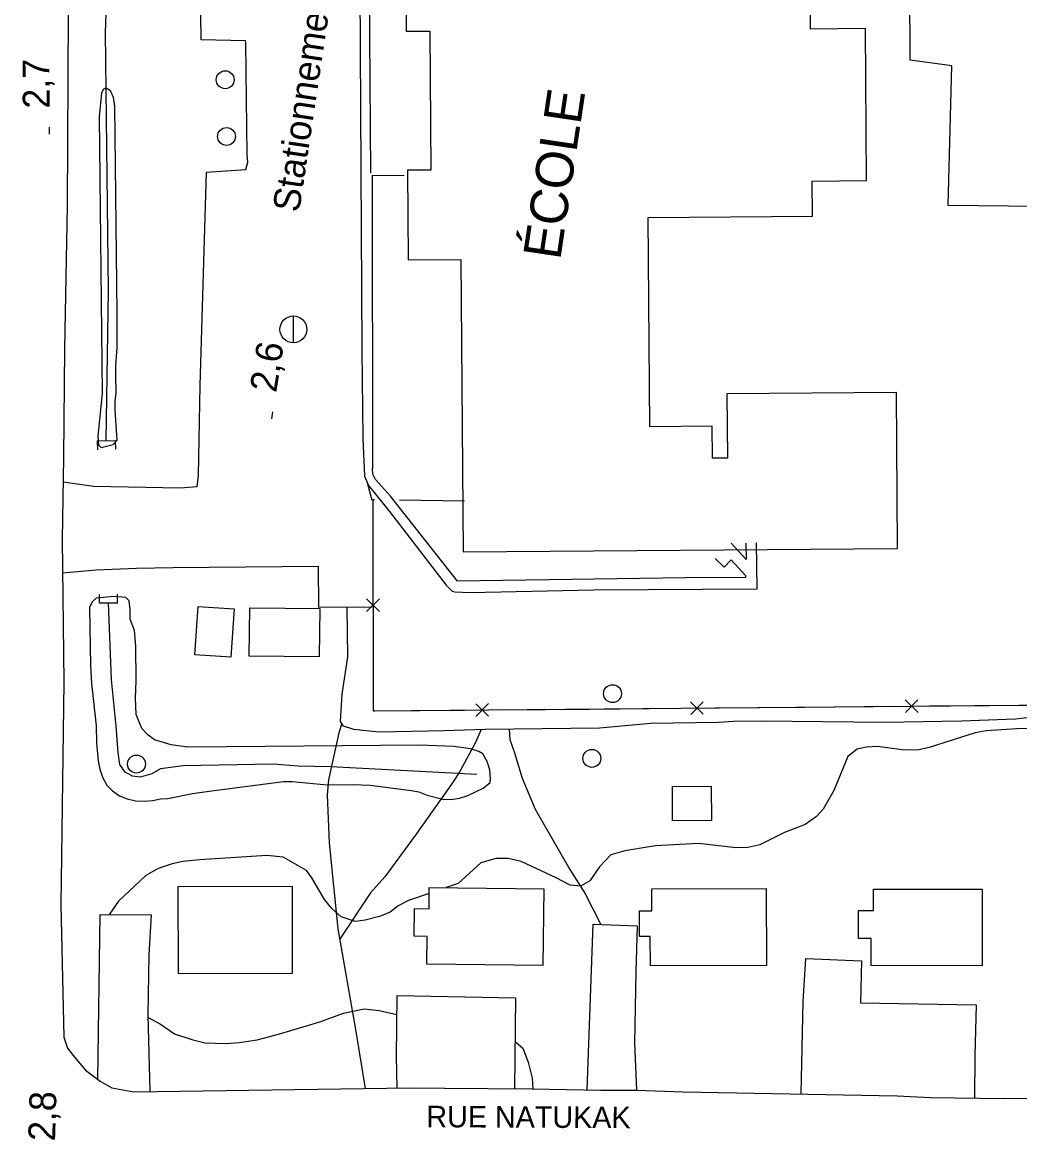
# Model space of a CAD drawing. Extents: x 282461 to 284471, y 5554090 to 5557646.
# Drawn here: x 283061.4 to 283172.9, y 5555298.4 to 5555423.2 of the extents above; entities that cross this region are included whole.
import ezdxf

# ---------------------------------------------------------------- set-up
doc = ezdxf.new("R2010")
doc.units = 0
for name, color, linetype in [('Niveau 15', 7, 'Continuous'), ('Niveau 19', 7, 'Continuous'), ('Niveau 2', 7, 'Continuous'), ('Niveau 21', 7, 'Continuous'), ('Niveau 22', 7, 'Continuous'), ('Niveau 26', 7, 'Continuous'), ('Niveau 3', 7, 'Continuous'), ('Niveau 31', 7, 'Continuous'), ('Niveau 36', 7, 'Continuous'), ('Niveau 37', 7, 'Continuous'), ('Niveau 4', 7, 'Continuous'), ('Niveau 52', 7, 'Continuous'), ('Niveau 56', 7, 'Continuous')]:
    doc.layers.add(name, color=color, linetype=linetype)

msp = doc.modelspace()

# ---------------------------------------------------------------- linework, layer by layer
at = {"layer": 'Niveau 19'}
for points in [[(283080.95, 5555371.34), (283079.03, 5555371.2), (283069.35, 5555371.38), (283065.96, 5555371.87)], [(283065.88, 5555361.73), (283069.65, 5555362.07), (283074.17, 5555362.23), (283078.23, 5555362.33), (283094.46, 5555362.46), (283094.52, 5555357.87), (283100.49, 5555357.94)], [(283069.84, 5555305.12), (283070.11, 5555323.54), (283075.79, 5555323.48), (283075.56, 5555319.02), (283075.45, 5555312.32), (283075.66, 5555303.75)], [(283124.54, 5555303.94), (283125.2, 5555322.46), (283130.13, 5555322.28), (283129.96, 5555317.12), (283129.83, 5555309.17), (283130.06, 5555303.9)], [(283148.44, 5555303.5), (283148.68, 5555313.8), (283148.97, 5555318.62), (283155.19, 5555318.36), (283155.07, 5555313.67), (283168.01, 5555313.43), (283167.85, 5555307.74), (283167.83, 5555303.01)], [(283103.3, 5555304.13), (283103.21, 5555307.67), (283103.31, 5555314.48), (283116.54, 5555314.22), (283116.42, 5555304.08)]]:
    msp.add_lwpolyline(points, dxfattribs=at)
at = {"layer": 'Niveau 2'}
for points in [[(283071.86, 5555383.86), (283071.85, 5555384.91), (283072, 5555386.88), (283072.01, 5555390.71), (283071.73, 5555413.87), (283071.6, 5555414.85), (283071.25, 5555415.6), (283070.78, 5555415.89), (283070.49, 5555415.77), (283070.26, 5555415.36), (283070, 5555412.69), (283070.32, 5555381.76), (283069.86, 5555376.99), (283069.93, 5555376.01), (283070.22, 5555375.72), (283071.55, 5555376.08), (283072.01, 5555376.55), (283071.8, 5555379.92), (283071.78, 5555380.9), (283071.89, 5555381.83), (283071.86, 5555383.86)], [(283073.47, 5555356.55), (283073.46, 5555357.59), (283073.33, 5555358.58), (283072.98, 5555358.98), (283071.58, 5555359.08), (283069.67, 5555358.88), (283069.21, 5555358.47), (283068.93, 5555357.83), (283069.01, 5555351.33), (283069.15, 5555349.36), (283069.67, 5555344.61), (283069.69, 5555342.69), (283069.89, 5555340.72), (283070.08, 5555339.79), (283070.38, 5555338.87), (283070.85, 5555338), (283071.5, 5555337.37), (283072.26, 5555336.8), (283073.14, 5555336.46), (283074.07, 5555336.24), (283075.05, 5555336.19), (283075.98, 5555336.26), (283076.85, 5555336.45), (283077.66, 5555336.51), (283080.44, 5555337.06), (283082.29, 5555337.32), (283090.58, 5555338.39), (283091.56, 5555338.41), (283095.46, 5555338.04), (283098.36, 5555338.07), (283100.27, 5555337.98), (283104.86, 5555337.39), (283105.74, 5555337.23), (283106.67, 5555336.89), (283108.42, 5555336.44), (283109.35, 5555336.4), (283110.27, 5555336.52), (283111.2, 5555336.82), (283112.93, 5555337.65), (283113.68, 5555338.3), (283113.73, 5555338.71), (283113.66, 5555339.69), (283113.36, 5555340.62), (283112.88, 5555341.48), (283112.41, 5555341.77), (283111.48, 5555342.05), (283109.62, 5555342.32), (283105.79, 5555342.45), (283079.91, 5555342.22), (283078.05, 5555342.49), (283076.19, 5555343.05), (283075.43, 5555343.63), (283074.78, 5555344.31), (283074.12, 5555345.87), (283074.04, 5555347.73), (283074.13, 5555349.7), (283074.09, 5555353.53), (283073.95, 5555355.27), (283073.47, 5555356.55)], [(283175.34, 5555344.31), (283172.55, 5555344.28), (283169.13, 5555344.07), (283167.92, 5555343.83), (283162.77, 5555342.2), (283161.44, 5555341.9), (283159.76, 5555341.94), (283156.97, 5555342.31), (283155.75, 5555342.24), (283154.71, 5555342), (283153.68, 5555341.18), (283152.1, 5555337.39), (283150.9, 5555335.29), (283150.16, 5555334.47), (283148.89, 5555333.58), (283146.58, 5555332.69), (283143.82, 5555331.32), (283142.49, 5555331.02), (283141.15, 5555331), (283136.97, 5555331.48), (283132.16, 5555331.2), (283128.74, 5555330.64), (283127.18, 5555330.21), (283125.92, 5555328.87), (283124.84, 5555327.29), (283123.8, 5555326.7), (283122.64, 5555326.8), (283121.07, 5555327.65), (283117.16, 5555329.47), (283115.7, 5555329.8), (283114.31, 5555329.78), (283112.64, 5555329.3), (283110.11, 5555327.01), (283108.78, 5555326.55)], [(283106.88, 5555325.89), (283104.57, 5555325.09), (283103.42, 5555324.5), (283102.5, 5555323.8), (283101.34, 5555323.32), (283099.72, 5555322.9), (283098.62, 5555322.77), (283097.05, 5555323.27), (283096, 5555324.19), (283095.17, 5555325.22), (283093.75, 5555327.64), (283093.16, 5555328.45), (283090.54, 5555329.93), (283088.74, 5555330.14), (283081.26, 5555329.65), (283079.35, 5555329.46), (283078.14, 5555329.21), (283076.58, 5555328.67), (283075.2, 5555327.91), (283072.16, 5555325.03), (283071.13, 5555323.57), (283071.11, 5555323.53)], [(283087.65, 5555309.54), (283090.02, 5555310.15), (283092.8, 5555310.99), (283094.76, 5555311.59), (283097.3, 5555312.49), (283099.61, 5555312.98), (283101.3, 5555312.82), (283103.28, 5555312.37)], [(283075.46, 5555312.02), (283076.85, 5555311.28), (283078.43, 5555310.2), (283080.35, 5555309.58), (283081.8, 5555309.19), (283084.18, 5555309.1), (283085.63, 5555309.23), (283087.65, 5555309.54)], [(283116.48, 5555309.35), (283117.35, 5555308.59), (283117.95, 5555307.03), (283118.38, 5555305.24), (283118.45, 5555304.05)]]:
    msp.add_lwpolyline(points, dxfattribs=at)
at = {"layer": 'Niveau 21'}
msp.add_lwpolyline([(283066.65, 5555446.03), (283066.43, 5555402.69), (283066.1, 5555386.79), (283066.02, 5555374.61), (283065.84, 5555365.45), (283066.03, 5555349.5), (283065.7, 5555324.61), (283066.05, 5555309.83), (283066.47, 5555308.61), (283067.24, 5555307.58), (283068.47, 5555306.14), (283070.12, 5555304.91), (283071.41, 5555304.17), (283073.85, 5555303.73), (283104.7, 5555304.15), (283108.59, 5555304.14), (283118.39, 5555304.07), (283126.06, 5555303.89), (283130.12, 5555303.9), (283135.23, 5555303.72), (283159.2, 5555303.28), (283162.91, 5555303.09), (283171.15, 5555302.97), (283177.99, 5555303.05)], dxfattribs=at)
at = {"layer": 'Niveau 22'}
for points in [[(283118.9, 5555456.44), (283102.1, 5555456.38), (283101.12, 5555456.28), (283100.34, 5555455.98), (283099.71, 5555455.39), (283099.34, 5555454.86), (283099.11, 5555454.14), (283098.9, 5555452.42), (283098.91, 5555449.26), (283099.05, 5555440.5), (283099.36, 5555386.62), (283099.48, 5555376.76), (283099.64, 5555372.52), (283100.09, 5555371.49), (283102.45, 5555368.58), (283108.76, 5555360.35), (283109.44, 5555359.69), (283109.76, 5555359.61), (283111.44, 5555359.54), (283125.24, 5555359.84), (283143.52, 5555359.93), (283143.48, 5555365.09)], [(283100.37, 5555406.39), (283100.14, 5555437.28), (283100.12, 5555452.06), (283100.22, 5555453.98), (283100.44, 5555454.47), (283100.7, 5555454.79), (283101.44, 5555455.12), (283106.06, 5555455.26), (283118.88, 5555455.35)], [(283138.86, 5555363.33), (283139.83, 5555362.36), (283140.63, 5555363.18), (283142.22, 5555361.43), (283142.22, 5555361.19), (283135.52, 5555361.18), (283110.03, 5555360.8), (283102.55, 5555370.3), (283100.89, 5555372.16), (283100.57, 5555372.74), (283100.55, 5555373.34)], [(283142.26, 5555365.05), (283142.29, 5555363.22), (283140.64, 5555365.03)], [(283180.17, 5555347.17), (283175.96, 5555345.77), (283172.42, 5555345.38), (283166.39, 5555345.14), (283157.81, 5555344.99), (283143.99, 5555345.16), (283140.91, 5555345.1), (283139.21, 5555344.98), (283131.66, 5555344.88), (283125.93, 5555344.35), (283113.14, 5555344.22), (283108.5, 5555344.05), (283101.25, 5555343.92), (283098.47, 5555344.2), (283097.31, 5555344.59), (283096.95, 5555345.11), (283097.16, 5555348.15), (283097.77, 5555352.32), (283097.71, 5555357.91)], [(283097.11, 5555344.87), (283096.79, 5555343.83), (283095.63, 5555338.57), (283095.47, 5555336.89), (283095.71, 5555331.56), (283096.66, 5555321.93), (283098.65, 5555310.7), (283099.72, 5555304.08)], [(283112.68, 5555344.2), (283112.06, 5555342.76), (283110.34, 5555339.58), (283109.49, 5555338.24), (283105.31, 5555332.37), (283101.91, 5555327.76), (283100.31, 5555325.95), (283096.86, 5555320.76)], [(283115.83, 5555344.26), (283115.89, 5555343.1), (283116.43, 5555341.6), (283117.27, 5555338.76), (283118.72, 5555335.32), (283122.61, 5555328.58), (283124.29, 5555325.92), (283126.07, 5555322.43)]]:
    msp.add_lwpolyline(points, dxfattribs=at)
at = {"layer": 'Niveau 26'}
for p, q in [((283069.76, 5555376.46), (283071.78, 5555376.53)), ((283069.76, 5555376.46), (283069.79, 5555375.46)), ((283071.78, 5555376.53), (283071.82, 5555375.53)), ((283070.04, 5555358.32), (283070.03, 5555359.31)), ((283072.06, 5555358.34), (283070.04, 5555358.32)), ((283072.06, 5555358.34), (283072.05, 5555359.34))]:
    msp.add_line(p, q, dxfattribs=at)
at = {"layer": 'Niveau 3'}
for p, q in [((283064.43, 5555410.73), (283064.43, 5555411.53)), ((283089.3, 5555378.94), (283089.42, 5555379.73))]:
    msp.add_line(p, q, dxfattribs=at)
at = {"layer": 'Niveau 31'}
for points in [[(283104.22, 5555432.21), (283104.29, 5555422.25), (283106.94, 5555422.27), (283107.07, 5555406.73), (283104.45, 5555406.71), (283104.53, 5555396.7), (283110.4, 5555396.75), (283110.66, 5555364.06), (283159.24, 5555364.45), (283159.11, 5555381.88), (283140.16, 5555381.73), (283140.22, 5555374.54), (283138.53, 5555374.52), (283138.51, 5555378.11), (283131.53, 5555378.05), (283131.35, 5555401.43), (283149.71, 5555401.57)], [(283149.71, 5555401.57), (283149.68, 5555405.51), (283155.77, 5555405.56), (283155.63, 5555422.55), (283149.49, 5555422.5), (283149.45, 5555426.54)], [(283085.07, 5555357.69), (283084.71, 5555352.31), (283080.7, 5555352.57), (283081.05, 5555357.95), (283085.07, 5555357.69)], [(283086.82, 5555357.81), (283094.64, 5555357.73), (283094.58, 5555352.32), (283086.76, 5555352.41), (283086.82, 5555357.81)], [(283138.44, 5555334.05), (283134.09, 5555334.02), (283134.07, 5555337.84), (283138.4, 5555337.87), (283138.44, 5555334.05)], [(283091.59, 5555326.67), (283078.8, 5555326.63), (283078.83, 5555316.94), (283091.62, 5555316.98), (283091.59, 5555326.67)], [(283106.89, 5555326.57), (283119.7, 5555326.42), (283119.59, 5555317.82), (283106.61, 5555317.97), (283106.65, 5555321.09), (283105.19, 5555321.11), (283105.23, 5555324.2), (283106.86, 5555324.18), (283106.89, 5555326.57)], [(283131.77, 5555326.4), (283144.53, 5555326.46), (283144.58, 5555317.85), (283131.61, 5555317.79), (283131.59, 5555321.09), (283130.4, 5555321.08), (283130.39, 5555323.93), (283131.78, 5555323.94), (283131.77, 5555326.4)], [(283156.53, 5555326.38), (283168.68, 5555326.36), (283168.67, 5555317.81), (283156.28, 5555317.82), (283156.28, 5555320.87), (283154.88, 5555320.87), (283154.88, 5555323.98), (283156.53, 5555323.98), (283156.53, 5555326.38)]]:
    msp.add_lwpolyline(points, dxfattribs=at)
at = {"layer": 'Niveau 36'}
msp.add_line((283091.7, 5555387.42), (283091.7, 5555390.42), dxfattribs=at)
for centre, radius in [((283084.08, 5555416.83), 1), ((283084.23, 5555410.49), 1), ((283091.7, 5555388.93), 1.5), ((283127.37, 5555348.22), 1), ((283074.16, 5555340.35), 1), ((283125.06, 5555340.98), 1)]:
    msp.add_circle(centre, radius, dxfattribs=at)
at = {"layer": 'Niveau 37'}
for p, q in [((283099.89, 5555358.81), (283101.31, 5555357.39)), ((283099.89, 5555357.39), (283101.31, 5555358.81)), ((283113.52, 5555345.69), (283112.1, 5555347.09)), ((283112.11, 5555345.68), (283113.51, 5555347.1)), ((283137.52, 5555345.91), (283136.09, 5555347.31)), ((283136.11, 5555345.89), (283137.51, 5555347.32)), ((283161.52, 5555346.12), (283160.09, 5555347.52)), ((283160.11, 5555346.11), (283161.51, 5555347.54))]:
    msp.add_line(p, q, dxfattribs=at)
for points in [[(283100.78, 5555369.89), (283100.57, 5555369.89), (283100.63, 5555346.28), (283173.73, 5555346.94), (283201.81, 5555359.78), (283219.05, 5555360.37), (283220.76, 5555366.73), (283218.89, 5555402.92), (283208.11, 5555416.06), (283175.14, 5555455.89), (283155.65, 5555489.95), (283159.82, 5555516.27), (283171.73, 5555531.64), (283156.94, 5555544.74), (283147.78, 5555551.39), (283136.32, 5555556.46), (283123.09, 5555561.58), (283102.03, 5555568.05), (283088.84, 5555529.18), (283085.74, 5555517.46), (283078.93, 5555485.69), (283074.88, 5555465.54), (283086.05, 5555465.69)], [(283104.08, 5555406.1), (283100.49, 5555406.12), (283100.55, 5555373.34)], [(283100.78, 5555369.89), (283100.57, 5555369.89), (283100.59, 5555360.1)], [(283110.83, 5555369.72), (283103.56, 5555369.84)], [(283110.83, 5555369.72), (283103.56, 5555369.84)], [(283100.61, 5555356.1), (283100.63, 5555346.28), (283100.81, 5555346.28)], [(283172.81, 5555346.93), (283173.73, 5555346.94), (283181.98, 5555350.71)], [(283100.81, 5555346.28), (283110.81, 5555346.37)], [(283114.81, 5555346.41), (283124.81, 5555346.5)], [(283124.81, 5555346.5), (283134.81, 5555346.59)], [(283138.81, 5555346.62), (283148.81, 5555346.71)], [(283148.81, 5555346.71), (283158.81, 5555346.81)], [(283162.81, 5555346.84), (283172.81, 5555346.93)]]:
    msp.add_lwpolyline(points, dxfattribs=at)
at = {"layer": 'Niveau 4'}
for points in [[(283070.76, 5555376.49), (283071.03, 5555393.29), (283070.7, 5555422.1), (283071.23, 5555437.09), (283070.84, 5555445.04), (283070.81, 5555452.12)], [(283112.21, 5555339.2), (283095.88, 5555340.04), (283092.22, 5555340.12), (283089.43, 5555340.32), (283079.39, 5555340.15), (283076.84, 5555339.83), (283075.87, 5555339.24), (283074.59, 5555338.88), (283073.72, 5555338.99), (283072.9, 5555339.44), (283072.31, 5555340.3), (283072.12, 5555341.64), (283071.91, 5555344.6), (283071.37, 5555349.79), (283071.04, 5555358.38)]]:
    msp.add_lwpolyline(points, dxfattribs=at)
at = {"layer": 'Niveau 52'}
for points in [[(283080.95, 5555371.34), (283081.1, 5555372.61), (283081.27, 5555382.65), (283081.98, 5555406.52), (283086.39, 5555406.8), (283086.61, 5555407.62), (283086.54, 5555408.43), (283086.39, 5555420.96), (283086.33, 5555421.19), (283081.4, 5555421.31), (283081.29, 5555429.78), (283081.32, 5555441.61), (283081.53, 5555451.93), (283081.63, 5555453.91)], [(283099.94, 5555371.82), (283100.47, 5555369.85)]]:
    msp.add_lwpolyline(points, dxfattribs=at)
at = {"layer": 'Niveau 56'}
msp.add_lwpolyline([(283181.75, 5555402.59), (283164.89, 5555402.78), (283165.3, 5555418.4), (283160.65, 5555419.01), (283160.43, 5555467.29), (283165.71, 5555466.46), (283165.9, 5555437.08), (283177.02, 5555436.21), (283176.86, 5555422.67), (283181.61, 5555422.47), (283181.75, 5555402.59)], dxfattribs=at)

# ---------------------------------------------------------------- texts
at = {"layer": 'Niveau 15'}
msp.add_text('RUE NATUKAK', height=2.4, rotation=359.719, dxfattribs=at).set_placement((283106.56, 5555299.76))
at = {"layer": 'Niveau 3'}
for s, rotation, p in [('2,7  ', 90.3163, (283064.46, 5555413.61)), ('2,6  ', 81.0957, (283089.78, 5555381.78)), ('2,8  ', 88.3077, (283065.06, 5555298.17))]:
    msp.add_text(s, height=3, rotation=rotation, dxfattribs=at).set_placement(p)
at = {"layer": 'Niveau 31'}
msp.add_text('ÉCOLE', height=4.2, rotation=81.5139, dxfattribs=at).set_placement((283121.52, 5555396.6))
at = {"layer": 'Niveau 52'}
msp.add_text('Stationnement', height=2.9999, rotation=81.5139, dxfattribs=at).set_placement((283092.34, 5555401.92))

doc.saveas('drawing.dxf')
